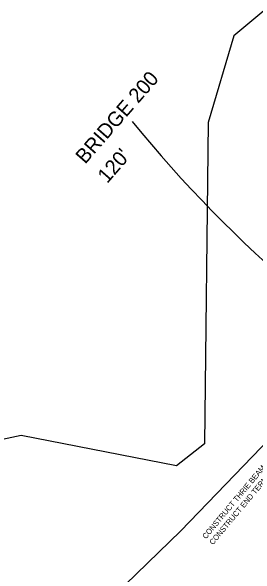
# Model space of a CAD drawing. Extents: x 2500794 to 2511032, y 910653 to 917533.
# Drawn here: x 2505369.8 to 2505570, y 913378 to 913839 of the extents above; entities that cross this region are included whole.
import ezdxf

# ---------------------------------------------------------------- set-up
doc = ezdxf.new("R2010")
doc.units = 0
for name, color, linetype in [('Default', 7, 'Continuous'), ('RD_EX_DV_Prop', 7, 'Continuous'), ('RD_EX_H2O_WetLd', 7, 'Continuous'), ('RD_EX_Wall', 7, 'Continuous'), ('RD_PD_MedBWall', 7, 'Continuous'), ('RD_PD_RW', 7, 'Continuous')]:
    doc.layers.add(name, color=color, linetype=linetype)

# ---------------------------------------------------------------- blocks, each defined once
blk = doc.blocks.new('Wetlands')
at = {"layer": 'Default'}
blk.add_lwpolyline([(636308.97, 231919.84), (636399.19, 232007.15), (636425.31, 232034.14), (636437.46, 232049.47), (636446.06, 232047.74), (636453.8, 232043.31), (636460.35, 232037.22), (636461.87, 232032.72), (636463.08, 232025.42), (636454.94, 232022.66), (636440.92, 232008.07), (636430.19, 231992.84)], dxfattribs=at)

msp = doc.modelspace()

# ---------------------------------------------------------------- linework, layer by layer
at = {"layer": 'RD_EX_DV_Prop'}
for p, q in [((2505604, 913862), (2505552, 913819)), ((2505552, 913819), (2505531, 913748)), ((2505531, 913748), (2505528, 913485)), ((2505378, 913492), (2505330, 913482)), ((2505505, 913467), (2505378, 913492)), ((2505528, 913485), (2505505, 913467))]:
    msp.add_line(p, q, dxfattribs=at)
at = {"layer": 'RD_EX_Wall'}
msp.add_arc((2506299.01, 914423.83), 1069.92, 219.1169, 240.15367, dxfattribs=at)
at = {"layer": 'RD_PD_RW'}
msp.add_arc((2504100.66, 914817.69), 2098.62, 314.20692, 318.31015, dxfattribs=at)

# ---------------------------------------------------------------- block references
at = {"layer": 'Default', "xscale": 3.937007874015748, "yscale": 3.937007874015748}
msp.add_blockref('Wetlands', (0, 0), dxfattribs=at)
at = {"layer": 'RD_EX_H2O_WetLd', "xscale": 3.937007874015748, "yscale": 3.937007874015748}
msp.add_blockref('Wetlands', (0, 0), dxfattribs=at)

# ---------------------------------------------------------------- texts
at = {"layer": 'RD_EX_Wall'}
for s, p in [('BRIDGE 200', (2505430.32, 913713.4)), ("120'", (2505448.4, 913697.62))]:
    msp.add_text(s, height=12, rotation=48.8976, dxfattribs=at).set_placement(p)
at = {"layer": 'RD_PD_MedBWall'}
for s, p in [('CONSTRUCT THRIE BEAM BRIDGE CONNECTOR', (2505529.27, 913406.92)), ('CONSTRUCT END TERMINAL (MT3)', (2505535.02, 913402.1))]:
    msp.add_text(s, height=4.5, rotation=50.0195, dxfattribs=at).set_placement(p)

doc.saveas('drawing.dxf')
